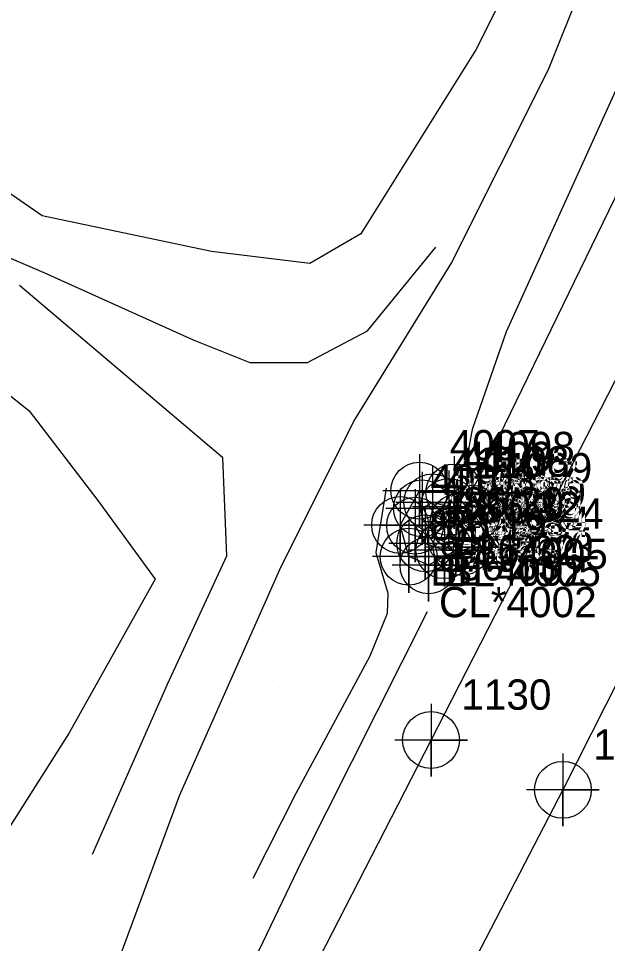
# Model space of a CAD drawing. Extents: x 2062781 to 2066835, y 358981 to 366501.
# Drawn here: x 2064036.6 to 2064085.2, y 361471.1 to 361547.4 of the extents above; entities that cross this region are included whole.
import ezdxf

# ---------------------------------------------------------------- set-up
doc = ezdxf.new("R2010")
doc.units = 0
for name, color, linetype in [('Exist DTM Breakline', 7, 'Continuous'), ('Exist DTM Breakline Cogo Comment', 7, 'Continuous'), ('Exist DTM Breakline Cogo Elevation', 7, 'Continuous'), ('Exist DTM Breakline Cogo Number', 7, 'Continuous'), ('Exist DTM Breakline Cogo Point CELL', 7, 'Continuous'), ('Exist DTM Crownline', 7, 'Continuous'), ('Exist DTM Crownline Cogo Number', 7, 'Continuous'), ('Exist DTM Crownline Cogo Point CELL', 7, 'Continuous'), ('Exist DTM Ridgeline', 7, 'Continuous'), ('Exist DTM Ridgeline Cogo Comment', 7, 'Continuous'), ('Exist DTM Ridgeline Cogo Elevation', 7, 'Continuous'), ('Exist DTM Ridgeline Cogo Number', 7, 'Continuous'), ('Exist DTM Ridgeline Cogo Point CELL', 7, 'Continuous'), ('Exist Roads EOP', 7, 'Continuous'), ('Exist Roads EOP Cogo Number', 7, 'Continuous'), ('Exist Roads EOP Cogo Point CELL', 7, 'Continuous'), ('PH Exist DTM Breakline', 7, 'Continuous'), ('PH Exist DTM Point', 7, 'Continuous')]:
    doc.layers.add(name, color=color, linetype=linetype)

msp = doc.modelspace()

# ---------------------------------------------------------------- linework, layer by layer
at = {"layer": 'Exist DTM Breakline'}
msp.add_lwpolyline([(2064069.311, 361505.551), (2064070.138, 361504.091), (2064071.721, 361503.529), (2064072.665, 361504.543), (2064072.892, 361505.857), (2064072.093, 361507.098), (2064070.729, 361507.472), (2064069.879, 361506.978)], dxfattribs=at)
at = {"layer": 'Exist DTM Breakline Cogo Point CELL'}
for points in [[(2064070.729, 361510.472), (2064070.729, 361504.472), (2064070.729, 361507.472), (2064073.729, 361507.472), (2064067.729, 361507.472)], [(2064070.729, 361510.472), (2064070.729, 361504.472), (2064070.729, 361507.472), (2064073.729, 361507.472), (2064067.729, 361507.472)], [(2064070.729, 361510.472), (2064070.729, 361504.472), (2064070.729, 361507.472), (2064073.729, 361507.472), (2064067.729, 361507.472)], [(2064069.879, 361509.978), (2064069.879, 361503.978), (2064069.879, 361506.978), (2064072.879, 361506.978), (2064066.879, 361506.978)], [(2064069.879, 361509.978), (2064069.879, 361503.978), (2064069.879, 361506.978), (2064072.879, 361506.978), (2064066.879, 361506.978)], [(2064069.879, 361509.978), (2064069.879, 361503.978), (2064069.879, 361506.978), (2064072.879, 361506.978), (2064066.879, 361506.978)], [(2064072.093, 361510.098), (2064072.093, 361504.098), (2064072.093, 361507.098), (2064075.093, 361507.098), (2064069.093, 361507.098)], [(2064072.093, 361510.098), (2064072.093, 361504.098), (2064072.093, 361507.098), (2064075.093, 361507.098), (2064069.093, 361507.098)], [(2064072.093, 361510.098), (2064072.093, 361504.098), (2064072.093, 361507.098), (2064075.093, 361507.098), (2064069.093, 361507.098)], [(2064069.311, 361508.551), (2064069.311, 361502.551), (2064069.311, 361505.551), (2064072.311, 361505.551), (2064066.311, 361505.551)], [(2064069.311, 361508.551), (2064069.311, 361502.551), (2064069.311, 361505.551), (2064072.311, 361505.551), (2064066.311, 361505.551)], [(2064069.311, 361508.551), (2064069.311, 361502.551), (2064069.311, 361505.551), (2064072.311, 361505.551), (2064066.311, 361505.551)], [(2064072.892, 361508.857), (2064072.892, 361502.857), (2064072.892, 361505.857), (2064075.892, 361505.857), (2064069.892, 361505.857)], [(2064072.892, 361508.857), (2064072.892, 361502.857), (2064072.892, 361505.857), (2064075.892, 361505.857), (2064069.892, 361505.857)], [(2064072.892, 361508.857), (2064072.892, 361502.857), (2064072.892, 361505.857), (2064075.892, 361505.857), (2064069.892, 361505.857)], [(2064072.665, 361507.543), (2064072.665, 361501.543), (2064072.665, 361504.543), (2064075.665, 361504.543), (2064069.665, 361504.543)], [(2064072.665, 361507.543), (2064072.665, 361501.543), (2064072.665, 361504.543), (2064075.665, 361504.543), (2064069.665, 361504.543)], [(2064072.665, 361507.543), (2064072.665, 361501.543), (2064072.665, 361504.543), (2064075.665, 361504.543), (2064069.665, 361504.543)], [(2064070.138, 361507.091), (2064070.138, 361501.091), (2064070.138, 361504.091), (2064073.138, 361504.091), (2064067.138, 361504.091)], [(2064070.138, 361507.091), (2064070.138, 361501.091), (2064070.138, 361504.091), (2064073.138, 361504.091), (2064067.138, 361504.091)], [(2064070.138, 361507.091), (2064070.138, 361501.091), (2064070.138, 361504.091), (2064073.138, 361504.091), (2064067.138, 361504.091)], [(2064071.721, 361506.529), (2064071.721, 361500.529), (2064071.721, 361503.529), (2064074.721, 361503.529), (2064068.721, 361503.529)], [(2064071.721, 361506.529), (2064071.721, 361500.529), (2064071.721, 361503.529), (2064074.721, 361503.529), (2064068.721, 361503.529)], [(2064071.721, 361506.529), (2064071.721, 361500.529), (2064071.721, 361503.529), (2064074.721, 361503.529), (2064068.721, 361503.529)]]:
    msp.add_lwpolyline(points, dxfattribs=at)
for centre in [(2064070.729, 361507.472), (2064070.729, 361507.472), (2064070.729, 361507.472), (2064069.879, 361506.978), (2064069.879, 361506.978), (2064069.879, 361506.978), (2064072.093, 361507.098), (2064072.093, 361507.098), (2064072.093, 361507.098), (2064072.892, 361505.857), (2064072.892, 361505.857), (2064072.892, 361505.857), (2064069.311, 361505.551), (2064069.311, 361505.551), (2064069.311, 361505.551), (2064072.665, 361504.543), (2064072.665, 361504.543), (2064072.665, 361504.543), (2064070.138, 361504.091), (2064070.138, 361504.091), (2064070.138, 361504.091), (2064071.721, 361503.529), (2064071.721, 361503.529), (2064071.721, 361503.529)]:
    msp.add_circle(centre, 2.344, dxfattribs=at)
at = {"layer": 'Exist DTM Crownline'}
msp.add_lwpolyline([(2064265.441, 361845.695), (2064239.974, 361795.637), (2064213.324, 361743.862), (2064188.563, 361695.075), (2064163.474, 361645.604), (2064134.868, 361589.208), (2064123.648, 361567.027), (2064102.768, 361525.754), (2064081.502, 361483.764), (2064060.491, 361443.216), (2064039.785, 361402.117), (2064017.952, 361359.285), (2063998.021, 361320.112), (2063977.861, 361280.752), (2063957.656, 361241.435), (2063938.488, 361203.846), (2063917.61, 361163.02), (2063896.2, 361120.913), (2063873.972, 361077.232), (2063852.927, 361035.552), (2063832.77, 360995.688), (2063813.378, 360956.989), (2063791.843, 360915.199), (2063771.297, 360874.466)], dxfattribs=at)
at = {"layer": 'Exist DTM Crownline Cogo Point CELL'}
msp.add_lwpolyline([(2064081.502, 361486.764), (2064081.502, 361480.764), (2064081.502, 361483.764), (2064084.502, 361483.764), (2064078.502, 361483.764)], dxfattribs=at)
msp.add_lwpolyline([(2064081.502, 361486.764), (2064081.502, 361480.764), (2064081.502, 361483.764), (2064084.502, 361483.764), (2064078.502, 361483.764)], dxfattribs=at)
msp.add_lwpolyline([(2064081.502, 361486.764), (2064081.502, 361480.764), (2064081.502, 361483.764), (2064084.502, 361483.764), (2064078.502, 361483.764)], dxfattribs=at)
msp.add_circle((2064081.502, 361483.764), 2.344, dxfattribs=at)
msp.add_circle((2064081.502, 361483.764), 2.344, dxfattribs=at)
msp.add_circle((2064081.502, 361483.764), 2.344, dxfattribs=at)
at = {"layer": 'Exist DTM Ridgeline'}
msp.add_lwpolyline([(2064068.068, 361505.599), (2064069.657, 361508.435), (2064072.542, 361508.284), (2064073.987, 361506.54), (2064073.151, 361503.783), (2064070.406, 361502.282), (2064068.78, 361502.997), (2064068.068, 361505.599)], dxfattribs=at)
at = {"layer": 'Exist DTM Ridgeline Cogo Point CELL'}
for points in [[(2064069.657, 361511.435), (2064069.657, 361505.435), (2064069.657, 361508.435), (2064072.657, 361508.435), (2064066.657, 361508.435)], [(2064069.657, 361511.435), (2064069.657, 361505.435), (2064069.657, 361508.435), (2064072.657, 361508.435), (2064066.657, 361508.435)], [(2064069.657, 361511.435), (2064069.657, 361505.435), (2064069.657, 361508.435), (2064072.657, 361508.435), (2064066.657, 361508.435)], [(2064072.542, 361511.284), (2064072.542, 361505.284), (2064072.542, 361508.284), (2064075.542, 361508.284), (2064069.542, 361508.284)], [(2064072.542, 361511.284), (2064072.542, 361505.284), (2064072.542, 361508.284), (2064075.542, 361508.284), (2064069.542, 361508.284)], [(2064072.542, 361511.284), (2064072.542, 361505.284), (2064072.542, 361508.284), (2064075.542, 361508.284), (2064069.542, 361508.284)], [(2064073.987, 361509.54), (2064073.987, 361503.54), (2064073.987, 361506.54), (2064076.987, 361506.54), (2064070.987, 361506.54)], [(2064073.987, 361509.54), (2064073.987, 361503.54), (2064073.987, 361506.54), (2064076.987, 361506.54), (2064070.987, 361506.54)], [(2064073.987, 361509.54), (2064073.987, 361503.54), (2064073.987, 361506.54), (2064076.987, 361506.54), (2064070.987, 361506.54)], [(2064068.068, 361508.599), (2064068.068, 361502.599), (2064068.068, 361505.599), (2064071.068, 361505.599), (2064065.068, 361505.599)], [(2064068.068, 361508.599), (2064068.068, 361502.599), (2064068.068, 361505.599), (2064071.068, 361505.599), (2064065.068, 361505.599)], [(2064068.068, 361508.599), (2064068.068, 361502.599), (2064068.068, 361505.599), (2064071.068, 361505.599), (2064065.068, 361505.599)], [(2064073.151, 361506.783), (2064073.151, 361500.783), (2064073.151, 361503.783), (2064076.151, 361503.783), (2064070.151, 361503.783)], [(2064073.151, 361506.783), (2064073.151, 361500.783), (2064073.151, 361503.783), (2064076.151, 361503.783), (2064070.151, 361503.783)], [(2064073.151, 361506.783), (2064073.151, 361500.783), (2064073.151, 361503.783), (2064076.151, 361503.783), (2064070.151, 361503.783)], [(2064068.78, 361505.997), (2064068.78, 361499.997), (2064068.78, 361502.997), (2064071.78, 361502.997), (2064065.78, 361502.997)], [(2064068.78, 361505.997), (2064068.78, 361499.997), (2064068.78, 361502.997), (2064071.78, 361502.997), (2064065.78, 361502.997)], [(2064068.78, 361505.997), (2064068.78, 361499.997), (2064068.78, 361502.997), (2064071.78, 361502.997), (2064065.78, 361502.997)], [(2064070.406, 361505.282), (2064070.406, 361499.282), (2064070.406, 361502.282), (2064073.406, 361502.282), (2064067.406, 361502.282)], [(2064070.406, 361505.282), (2064070.406, 361499.282), (2064070.406, 361502.282), (2064073.406, 361502.282), (2064067.406, 361502.282)], [(2064070.406, 361505.282), (2064070.406, 361499.282), (2064070.406, 361502.282), (2064073.406, 361502.282), (2064067.406, 361502.282)]]:
    msp.add_lwpolyline(points, dxfattribs=at)
for centre in [(2064069.657, 361508.435), (2064069.657, 361508.435), (2064069.657, 361508.435), (2064072.542, 361508.284), (2064072.542, 361508.284), (2064072.542, 361508.284), (2064073.987, 361506.54), (2064073.987, 361506.54), (2064073.987, 361506.54), (2064068.068, 361505.599), (2064068.068, 361505.599), (2064068.068, 361505.599), (2064073.151, 361503.783), (2064073.151, 361503.783), (2064073.151, 361503.783), (2064068.78, 361502.997), (2064068.78, 361502.997), (2064068.78, 361502.997), (2064070.406, 361502.282), (2064070.406, 361502.282), (2064070.406, 361502.282)]:
    msp.add_circle(centre, 2.344, dxfattribs=at)
at = {"layer": 'Exist Roads EOP'}
msp.add_lwpolyline([(2063947.544, 361247.655), (2063967.277, 361286.12), (2063986.626, 361323.879), (2064008.237, 361366.151), (2064030.201, 361409.405), (2064050.535, 361448.686), (2064070.623, 361487.87), (2064093.973, 361533.433), (2064113.626, 361572.45), (2064134.872, 361614.055), (2064156.049, 361655.626), (2064176.927, 361697.028), (2064198.396, 361739.791), (2064219.665, 361781.226), (2064239.904, 361821.078), (2064255.886, 361852.537)], dxfattribs=at)
at = {"layer": 'Exist Roads EOP Cogo Point CELL'}
msp.add_lwpolyline([(2064070.623, 361490.87), (2064070.623, 361484.87), (2064070.623, 361487.87), (2064073.623, 361487.87), (2064067.623, 361487.87)], dxfattribs=at)
msp.add_lwpolyline([(2064070.623, 361490.87), (2064070.623, 361484.87), (2064070.623, 361487.87), (2064073.623, 361487.87), (2064067.623, 361487.87)], dxfattribs=at)
msp.add_lwpolyline([(2064070.623, 361490.87), (2064070.623, 361484.87), (2064070.623, 361487.87), (2064073.623, 361487.87), (2064067.623, 361487.87)], dxfattribs=at)
msp.add_circle((2064070.623, 361487.87), 2.344, dxfattribs=at)
msp.add_circle((2064070.623, 361487.87), 2.344, dxfattribs=at)
msp.add_circle((2064070.623, 361487.87), 2.344, dxfattribs=at)
at = {"layer": 'PH Exist DTM Breakline'}
for points in [[(2064136.92, 361676.987), (2064126.8, 361656.825), (2064107.827, 361619.934), (2064089.288, 361582.584), (2064082.279, 361560.595), (2064074.307, 361544.794), (2064064.839, 361529.604), (2064060.626, 361527.167), (2064052.5, 361528.155), (2064038.542, 361531.109), (2064030.927, 361536.342), (2064024.795, 361540.375), (2064016.897, 361540.46), (2064015.152, 361536.984), (2064016.858, 361531.892), (2064023.558, 361526.112), (2064037.465, 361515.029), (2064043.133, 361507.623), (2064047.858, 361501.149), (2064040.757, 361488.475), (2064035.678, 361480.426), (2064032.627, 361471.633)], [(2064145.694, 361672.608), (2064136.014, 361655.307), (2064122.724, 361628.828), (2064111.045, 361605.561), (2064106.105, 361594.61), (2064102.41, 361585.924), (2064099.601, 361579.451), (2064093.806, 361575.981), (2064088.732, 361564.216), (2064080.274, 361543.145), (2064072.302, 361527.262), (2064064.321, 361514.323), (2064058.227, 361502.149), (2064049.862, 361483.315), (2064044.105, 361467.791), (2064039.194, 361459.084), (2064033.036, 361454.508), (2064023.41, 361449.148), (2064017.147, 361445.606), (2064011.127, 361443.228), (2063996.992, 361437.141), (2063986.604, 361434.879)], [(2064157.636, 361670.668), (2064144.946, 361648.116), (2064132.684, 361625.091), (2064120.272, 361602.15), (2064104.593, 361569.587), (2064091.497, 361544.323), (2064076.204, 361512.861), (2064074.988, 361510.257), (2064073.823, 361508.184)], [(2064152.12, 361669.425), (2064135.907, 361639.637), (2064121.754, 361613.492), (2064110.383, 361589.099), (2064100.139, 361572.479), (2064090.136, 361550.895), (2064076.815, 361521.541), (2064074.014, 361513.479), (2064073.428, 361510.409)], [(2064018.191, 361537.61), (2064027.015, 361531.412), (2064038.671, 361526.434), (2064050.982, 361520.878), (2064055.667, 361518.991), (2064060.427, 361518.994), (2064065.368, 361521.622), (2064071.022, 361528.519)], [(2064042.694, 361478.449), (2064048.867, 361492.486), (2064053.766, 361503.059), (2064053.454, 361511.14), (2064046.962, 361516.641), (2064036.654, 361525.361)], [(2064066.911, 361508.646), (2064066.073, 361503.335), (2064067.048, 361499.981), (2064066.995, 361498.305), (2064065.562, 361494.788), (2064059.47, 361483.476), (2064055.907, 361476.46)], [(2064070.302, 361498.439), (2064059.896, 361477.789), (2064049.435, 361455.954), (2064043.492, 361446.959)]]:
    msp.add_lwpolyline(points, dxfattribs=at)
at = {"layer": 'PH Exist DTM Point'}
for p, q in [((2064055.132, 361535.384), (2064055.132, 361535.384)), ((2064078.414, 361532.228), (2064078.414, 361532.228)), ((2064055.132, 361515.384), (2064055.132, 361515.384)), ((2064057.509, 361492.76), (2064057.509, 361492.76)), ((2064052.51, 361474.619), (2064052.51, 361474.619)), ((2064037.946, 361472.697), (2064037.946, 361472.697))]:
    msp.add_line(p, q, dxfattribs=at)

# ---------------------------------------------------------------- texts
at = {"layer": 'Exist DTM Breakline Cogo Comment'}
for s, p in [('EL*4005', (2064072.379, 361501.978)), ('EL*4005', (2064072.379, 361501.978)), ('EL*4005', (2064072.379, 361501.978)), ('BL*4005', (2064071.811, 361500.551)), ('BL*4005', (2064071.811, 361500.551)), ('BL*4005', (2064071.811, 361500.551))]:
    msp.add_text(s, height=2.5, dxfattribs=at).set_placement(p)
at = {"layer": 'Exist DTM Breakline Cogo Elevation'}
for s, p in [('86.09', (2064072.379, 361505.728)), ('86.09', (2064072.379, 361505.728)), ('86.09', (2064072.379, 361505.728)), ('86.20', (2064073.229, 361506.222)), ('86.20', (2064073.229, 361506.222)), ('86.20', (2064073.229, 361506.222)), ('86.32', (2064074.593, 361505.848)), ('86.32', (2064074.593, 361505.848)), ('86.32', (2064074.593, 361505.848)), ('86.19', (2064071.811, 361504.301)), ('86.19', (2064071.811, 361504.301)), ('86.19', (2064071.811, 361504.301)), ('86.34', (2064075.392, 361504.607)), ('86.34', (2064075.392, 361504.607)), ('86.34', (2064075.392, 361504.607)), ('86.26', (2064072.638, 361502.841)), ('86.26', (2064072.638, 361502.841)), ('86.26', (2064072.638, 361502.841)), ('86.37', (2064075.165, 361503.293)), ('86.37', (2064075.165, 361503.293)), ('86.37', (2064075.165, 361503.293)), ('86.32', (2064074.221, 361502.279)), ('86.32', (2064074.221, 361502.279)), ('86.32', (2064074.221, 361502.279))]:
    msp.add_text(s, height=2.5, dxfattribs=at).set_placement(p)
at = {"layer": 'Exist DTM Breakline Cogo Number'}
for s, p in [('4110', (2064072.379, 361509.478)), ('4110', (2064072.379, 361509.478)), ('4110', (2064072.379, 361509.478)), ('4109', (2064073.229, 361509.972)), ('4109', (2064073.229, 361509.972)), ('4109', (2064073.229, 361509.972)), ('4108', (2064074.593, 361509.598)), ('4108', (2064074.593, 361509.598)), ('4108', (2064074.593, 361509.598)), ('4103', (2064071.811, 361508.051)), ('4103', (2064071.811, 361508.051)), ('4103', (2064071.811, 361508.051)), ('4107', (2064075.392, 361508.357)), ('4107', (2064075.392, 361508.357)), ('4107', (2064075.392, 361508.357)), ('4104', (2064072.638, 361506.591)), ('4104', (2064072.638, 361506.591)), ('4104', (2064072.638, 361506.591)), ('4106', (2064075.165, 361507.043)), ('4106', (2064075.165, 361507.043)), ('4106', (2064075.165, 361507.043)), ('4105', (2064074.221, 361506.029)), ('4105', (2064074.221, 361506.029)), ('4105', (2064074.221, 361506.029))]:
    msp.add_text(s, height=2.5, dxfattribs=at).set_placement(p)
at = {"layer": 'Exist DTM Crownline Cogo Number'}
msp.add_text('1158', height=2.5, dxfattribs=at).set_placement((2064084.002, 361486.264))
msp.add_text('1158', height=2.5, dxfattribs=at).set_placement((2064084.002, 361486.264))
msp.add_text('1158', height=2.5, dxfattribs=at).set_placement((2064084.002, 361486.264))
at = {"layer": 'Exist DTM Ridgeline Cogo Comment'}
for s, p in [('BL*4002', (2064070.568, 361500.6)), ('BL*4002', (2064070.568, 361500.6)), ('BL*4002', (2064070.568, 361500.6)), ('CL*4002', (2064071.28, 361497.997)), ('CL*4002', (2064071.28, 361497.997)), ('CL*4002', (2064071.28, 361497.997))]:
    msp.add_text(s, height=2.5, dxfattribs=at).set_placement(p)
at = {"layer": 'Exist DTM Ridgeline Cogo Elevation'}
for s, p in [('87.29', (2064072.157, 361507.185)), ('87.29', (2064072.157, 361507.185)), ('87.29', (2064072.157, 361507.185)), ('86.89', (2064075.042, 361507.034)), ('86.89', (2064075.042, 361507.034)), ('86.89', (2064075.042, 361507.034)), ('86.94', (2064076.487, 361505.29)), ('86.94', (2064076.487, 361505.29)), ('86.94', (2064076.487, 361505.29)), ('87.29', (2064070.568, 361504.35)), ('87.29', (2064070.568, 361504.35)), ('87.29', (2064070.568, 361504.35)), ('86.73', (2064075.651, 361502.533)), ('86.73', (2064075.651, 361502.533)), ('86.73', (2064075.651, 361502.533)), ('87.07', (2064071.28, 361501.747)), ('87.07', (2064071.28, 361501.747)), ('87.07', (2064071.28, 361501.747)), ('86.83', (2064072.906, 361501.032)), ('86.83', (2064072.906, 361501.032)), ('86.83', (2064072.906, 361501.032))]:
    msp.add_text(s, height=2.5, dxfattribs=at).set_placement(p)
at = {"layer": 'Exist DTM Ridgeline Cogo Number'}
for s, p in [('4097', (2064072.157, 361510.935)), ('4097', (2064072.157, 361510.935)), ('4097', (2064072.157, 361510.935)), ('4098', (2064075.042, 361510.784)), ('4098', (2064075.042, 361510.784)), ('4098', (2064075.042, 361510.784)), ('4099', (2064076.487, 361509.04)), ('4099', (2064076.487, 361509.04)), ('4099', (2064076.487, 361509.04)), ('4096', (2064070.568, 361508.1)), ('4096', (2064070.568, 361508.1)), ('4096', (2064070.568, 361508.1)), ('4100', (2064075.651, 361506.283)), ('4100', (2064075.651, 361506.283)), ('4100', (2064075.651, 361506.283)), ('4102', (2064071.28, 361505.497)), ('4102', (2064071.28, 361505.497)), ('4102', (2064071.28, 361505.497)), ('4101', (2064072.906, 361504.782)), ('4101', (2064072.906, 361504.782)), ('4101', (2064072.906, 361504.782))]:
    msp.add_text(s, height=2.5, dxfattribs=at).set_placement(p)
at = {"layer": 'Exist Roads EOP Cogo Number'}
msp.add_text('1130', height=2.5, dxfattribs=at).set_placement((2064073.123, 361490.37))
msp.add_text('1130', height=2.5, dxfattribs=at).set_placement((2064073.123, 361490.37))
msp.add_text('1130', height=2.5, dxfattribs=at).set_placement((2064073.123, 361490.37))

doc.saveas('drawing.dxf')
